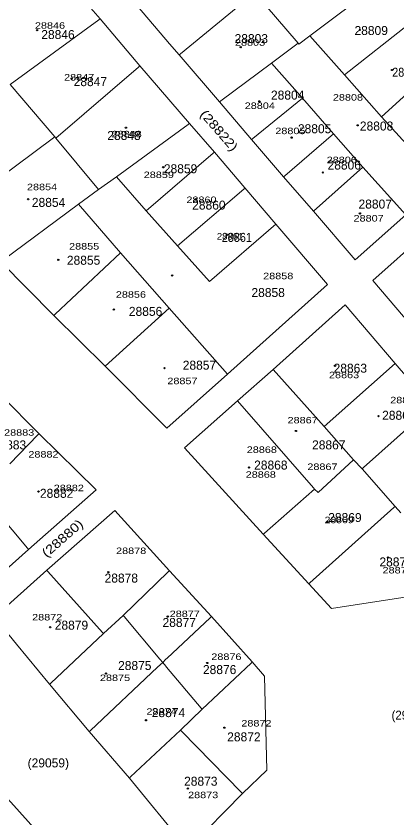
# Model space of a CAD drawing. Extents: x 650553 to 652508, y 239277 to 241647.
# Drawn here: x 651055.5 to 651208.2, y 240108.2 to 240429.4 of the extents above; entities that cross this region are included whole.
import ezdxf

# ---------------------------------------------------------------- set-up
doc = ezdxf.new("R2010")
doc.units = 0
doc.header["$PDMODE"] = 32
doc.header["$PDSIZE"] = 0.5
for name, color, linetype in [('19', 7, 'Continuous'), ('20', 7, 'Continuous'), ('6', 7, 'Continuous')]:
    doc.layers.add(name, color=color, linetype=linetype)
doc.layers.add('3', color=7, linetype='Continuous', lineweight=13)
doc.layers.add('5', color=7, linetype='Continuous', lineweight=13)

msp = doc.modelspace()

# ---------------------------------------------------------------- linework, layer by layer
at = {"layer": '3'}
msp.add_line((651158.48, 240287.8), (651144.21, 240275.25), dxfattribs=at)
for points in [[(651159.62, 240345.99), (651147.22, 240360.49), (651134.98, 240374.83), (651124.99, 240386.29), (651105.04, 240409.37), (651089.17, 240428.21), (651074.25, 240445.5), (651059.43, 240462.76), (651045.38, 240479.28), (651030.5, 240496.7), (651007.34, 240523.33)], [(650963.52, 240488.81), (650925.94, 240459.4), (650925.48, 240455.02), (650945.81, 240434.62), (650961.6, 240418.64), (650977.42, 240402.86), (650993.66, 240386.64), (651010.27, 240370.23), (651029.97, 240350.43), (651049.39, 240330.95), (651070.65, 240309.46), (651091.16, 240289.1)], [(651120.85, 240413.8), (651116.99, 240418.28), (651110.95, 240425.36), (651101.09, 240436.99), (651086.43, 240454.1), (651071.45, 240471.3), (651057.52, 240487.67)], [(651174.64, 240351.27), (651162.73, 240364.92), (651149.87, 240379.87), (651137.01, 240394.99), (651120.85, 240413.8)], [(651220.02, 240298.27), (651198.5, 240323.44), (651219.19, 240341.88), (651236.46, 240357.1)], [(651174.64, 240351.27), (651191.4, 240331.77), (651211.64, 240349.75)], [(651140.16, 240285.96), (651180.24, 240321.86), (651159.62, 240345.99)], [(651087.57, 240239.54), (651064.69, 240262.07), (651049.64, 240277.24), (651033.12, 240293.56), (651019.23, 240307.86), (651002.88, 240324.42)], [(651207.46, 240290.15), (651187.44, 240313.63), (651158.48, 240287.8)], [(651091.16, 240289.1), (651115.86, 240264.33), (651140.16, 240285.96)], [(651255.84, 240233.78), (651235.77, 240257.09), (651222.25, 240273), (651207.46, 240290.15)], [(651144.21, 240275.25), (651122.95, 240256.37), (651154.5, 240221.82), (651172.78, 240201.91)], [(651004.69, 240237.82), (651035.18, 240202.17), (651035.94, 240202.81), (651036.11, 240202.584), (651036.41, 240201.81), (651037.555, 240200.241), (651039.578, 240199.34), (651041.891, 240199.7), (651043.384, 240201.007), (651044.011, 240202.539), (651044.251, 240202.72), (651045, 240202.01), (651060.45, 240215.71), (651087.57, 240239.54)], [(651172.78, 240201.91), (651181.85, 240192.05), (651219.16, 240197.79), (651228.97, 240207.08), (651255.84, 240233.78)], [(651046.67, 240188.64), (651067.79, 240207.42), (651095.04, 240231.27)], [(651095.04, 240231.27), (651116.94, 240207.2), (651133.8, 240188.82), (651150.16, 240170.67)], [(651068.91, 240161.72), (651055.65, 240177.73), (651046.67, 240188.64)], [(651150.16, 240170.67), (651155.11, 240165.02), (651155.97, 240127.38), (651146.21, 240118.01)], [(651146.21, 240118.01), (651125.2, 240096.68), (651124.15, 240096.5), (651123.22, 240096.94), (651100.89, 240124.15), (651084.81, 240142.79), (651068.91, 240161.72)], [(651014.69, 240119.32), (651031.37, 240136.47), (651033.06, 240136.27), (651053.41, 240114.49), (651063.76, 240102.95), (651079.09, 240086.95)]]:
    msp.add_lwpolyline(points, dxfattribs=at)
at = {"layer": '5'}
for p, q in [((651187.18, 240405.87), (651173.28, 240421.43)), ((651201.93, 240389.04), (651187.18, 240405.87)), ((651088.54, 240359.9), (651071.47, 240380.47)), ((651097.37, 240334.49), (651080.47, 240353.97)), ((651159.62, 240345.99), (651133, 240323.04)), ((651116.84, 240312.34), (651091.16, 240289.1)), ((651158.48, 240287.8), (651178.96, 240264.97)), ((651207.46, 240290.15), (651178.96, 240264.97)), ((651178.96, 240264.97), (651190.76, 240251.59))]:
    msp.add_line(p, q, dxfattribs=at)
for points in [[(651173.28, 240421.43), (651199.84, 240441.424), (651200.34, 240441.8)], [(651120.85, 240413.8), (651121.35, 240414.213), (651151.16, 240438.82), (651168.49, 240418.45)], [(651089.17, 240428.21), (651088.67, 240427.846), (651053.14, 240401.96)], [(651187.18, 240405.87), (651212.91, 240426.077), (651213.41, 240426.47)], [(651168.49, 240418.45), (651168.79, 240418.12), (651173.28, 240421.43)], [(651194.44, 240368.84), (651182.73, 240382.13), (651170.27, 240396.41), (651157.82, 240410.51), (651168.49, 240418.45)], [(651071.47, 240380.47), (651104.54, 240408.94), (651105.04, 240409.37)], [(651137.01, 240394.99), (651137.51, 240395.363), (651157.82, 240410.51)], [(651225.94, 240362.65), (651201.93, 240389.04), (651226.59, 240411.22)], [(651071.47, 240380.47), (651070.98, 240381.01), (651053.14, 240401.96)], [(651149.87, 240379.87), (651150.37, 240380.275), (651170.27, 240396.41)], [(651095.77, 240365.01), (651124.49, 240385.926), (651124.99, 240386.29)], [(651029.97, 240350.43), (651030.47, 240350.803), (651070.98, 240381.01)], [(651162.73, 240364.92), (651163.23, 240365.35), (651182.73, 240382.13)], [(651107.58, 240351.32), (651134.48, 240374.401), (651134.98, 240374.83)], [(651174.64, 240351.27), (651194.44, 240368.84), (651211.64, 240349.75)], [(651049.39, 240330.95), (651049.89, 240331.32), (651080.47, 240353.97), (651088.54, 240359.9), (651095.77, 240365.01)], [(651133, 240323.04), (651120.13, 240337.27), (651107.58, 240351.32), (651095.77, 240365.01)], [(651147.22, 240360.49), (651146.72, 240360.061), (651120.13, 240337.27)], [(651097.37, 240334.49), (651071.15, 240309.928), (651070.65, 240309.46)], [(651140.16, 240285.96), (651116.84, 240312.34), (651097.37, 240334.49)], [(651144.21, 240275.25), (651174.674, 240240.35), (651175.11, 240239.85)], [(651222.25, 240273), (651221.75, 240272.555), (651194.72, 240248.495), (651194.22, 240248.05)], [(651052.92, 240250), (651064.202, 240261.57), (651064.69, 240262.07)], [(651190.76, 240251.59), (651176.6, 240238.55), (651175.11, 240239.85)], [(651190.76, 240251.59), (651194.22, 240248.05), (651207.38, 240232.92), (651209.75, 240230.35)], [(651175.11, 240239.85), (651155, 240222.257), (651154.5, 240221.82)], [(651041.44, 240238.23), (651060.028, 240216.21), (651060.45, 240215.71)], [(651207.38, 240232.92), (651206.88, 240232.472), (651173.28, 240202.358), (651172.78, 240201.91)], [(651067.79, 240207.42), (651068.238, 240206.92), (651090.112, 240182.52), (651090.56, 240182.02)], [(651098.39, 240189.31), (651116.44, 240206.718), (651116.94, 240207.2)], [(651068.91, 240161.72), (651069.41, 240162.189), (651090.56, 240182.02), (651098.39, 240189.31)], [(651098.39, 240189.31), (651098.812, 240188.81), (651113.15, 240171.84), (651114.34, 240170.49)], [(651114.34, 240170.49), (651115.45, 240171.8), (651115.99, 240172.22), (651133.3, 240188.354), (651133.8, 240188.82)], [(651084.81, 240142.79), (651085.31, 240143.261), (651112.13, 240168.52), (651114.34, 240170.49)], [(651114.34, 240170.49), (651115.49, 240169.03), (651115.78, 240168.55), (651129.656, 240152.2), (651130.08, 240151.7)], [(651130.08, 240151.7), (651149.66, 240170.198), (651150.16, 240170.67)], [(651100.89, 240124.15), (651101.39, 240124.619), (651121.38, 240143.37), (651130.08, 240151.7)], [(651121.38, 240143.37), (651121.87, 240142.87), (651145.72, 240118.51), (651146.21, 240118.01)]]:
    msp.add_lwpolyline(points, dxfattribs=at)
at = {"layer": '6'}
for p in [(651063.944, 240423.73), (651193.265, 240423.835), (651145.512, 240416.905), (651206.159, 240407.755), (651077.802, 240404.34), (651153.022, 240395.19), (651099.513, 240384.635), (651192.39, 240385.59), (651165.939, 240380.665), (651114.47, 240368.805), (651178.414, 240366.7), (651060.309, 240355.98), (651127.567, 240356.05), (651193.305, 240350.305), (651140.047, 240341.765), (651072.415, 240331.715), (651118.037, 240325.485), (651094.69, 240311.795), (651114.992, 240288.335), (651183.33, 240289.3), (651200.752, 240269.1), (651167.647, 240263.175), (651148.817, 240248.535), (651064.457, 240238.89), (651180.316, 240226.75), (651204.542, 240212.485), (651092.424, 240206.645), (651116.28, 240188.845), (651069.147, 240184.57), (651132.123, 240170.26), (651091.518, 240166.05), (651107.563, 240147.32), (651138.988, 240144.34), (651124.337, 240119.935)]:
    msp.add_point(p, dxfattribs=at)

# ---------------------------------------------------------------- texts
at = {"layer": '19'}
for s, p in [('28809', (651191.131, 240421.756)), ('28846', (651065.591, 240420.139)), ('28803', (651143.073, 240418.523)), ('28847', (651078.55, 240401.28)), ('28804', (651157.652, 240395.893)), ('28808', (651193.289, 240383.5)), ('28805', (651168.451, 240382.422)), ('28848', (651092.048, 240379.727)), ('28806', (651180.331, 240367.874)), ('28859', (651114.727, 240366.39)), ('28854', (651061.809, 240352.919)), ('28860', (651126.066, 240351.841)), ('28807', (651192.75, 240352.248)), ('28855', (651075.849, 240329.749)), ('28858', (651149.824, 240316.818)), ('28856', (651100.688, 240309.274)), ('28857', (651122.287, 240287.721)), ('28863', (651182.759, 240286.511)), ('28864', (651202.198, 240267.652)), ('28883', (651046.148, 240255.798)), ('28867', (651174.12, 240255.799)), ('28868', (651150.902, 240247.716)), ('28882', (651065.047, 240236.4)), ('28869', (651180.6, 240226.702)), ('28870', (651201.118, 240208.921)), ('28878', (651090.965, 240202.454)), ('28877', (651114.184, 240184.673)), ('28879', (651070.986, 240183.595)), ('28875', (651096.365, 240167.431)), ('28876', (651130.383, 240165.814)), ('28874', (651109.863, 240148.572)), ('28872', (651140.102, 240138.873)), ('(29059)', (651060.114, 240128.435)), ('28873', (651122.823, 240121.091))]:
    msp.add_text(s, height=3.6, dxfattribs=at).set_placement(p)
for s, width, p in [('28810', 0.9, (651206.249, 240405.053)), ('28861', 0.9, (651137.946, 240338.909)), ('(29418)', 0.95, (651205.987, 240147.56))]:
    msp.add_text(s, height=3.6, dxfattribs=dict(at, width=width)).set_placement(p)
at = {"layer": '19', "width": 1.2}
for s, rotation, p in [('(28822)', 311.08, (651128.945, 240389.856)), ('(28880)', 41.193, (651067.746, 240212.284))]:
    msp.add_text(s, height=3.6, rotation=rotation, dxfattribs=at).set_placement(p)
at = {"layer": '20'}
for s, width, p in [('28846', 1.25, (651063.037, 240424.268)), ('28803', 1.25, (651143.211, 240417.442)), ('28847', 1.25, (651074.732, 240403.52)), ('28808', 1.25, (651182.457, 240395.486)), ('28804', 1.25, (651147.12, 240392.142)), ('28805', 1.25, (651159.383, 240382.054)), ('28848', 1.25, (651093.776, 240380.772)), ('28806', 1.25, (651179.976, 240370.423)), ('28859', 1.25, (651106.653, 240364.473)), ('28854', 1.25, (651059.851, 240359.595)), ('28860', 1.25, (651123.761, 240354.467)), ('28807', 1.25, (651190.738, 240347.048)), ('28861', 1.1, (651135.95, 240339.826)), ('28855', 1.25, (651076.726, 240335.824)), ('28858', 1.25, (651154.524, 240323.949)), ('28856', 1.25, (651095.473, 240316.531)), ('28857', 1.25, (651116.115, 240281.908)), ('28863', 1.25, (651180.894, 240284.307)), ('28864', 1.25, (651205.438, 240274.246)), ('28867', 1.25, (651164.295, 240266.202)), ('28883', 1.25, (651050.686, 240261.259)), ('28868', 1.25, (651147.946, 240254.374)), ('28882', 1.25, (651060.405, 240252.518)), ('28867', 1.25, (651172.233, 240247.555)), ('28868', 1.25, (651147.519, 240244.421)), ('28882', 1.25, (651070.58, 240239.064)), ('28869', 1.2, (651179.157, 240226.242)), ('28878', 1.25, (651095.573, 240213.888)), ('28870', 1.25, (651202.366, 240206.116)), ('28877', 1.25, (651117.051, 240188.637)), ('28872', 1.25, (651061.916, 240187.288)), ('28876', 1.25, (651133.732, 240171.47)), ('28875', 1.25, (651089.101, 240163.021)), ('28874', 1.25, (651107.744, 240149.514)), ('28872', 1.25, (651145.77, 240144.812)), ('28873', 1.25, (651124.432, 240116.112))]:
    msp.add_text(s, height=2.6, dxfattribs=dict(at, width=width)).set_placement(p)

doc.saveas('drawing.dxf')
